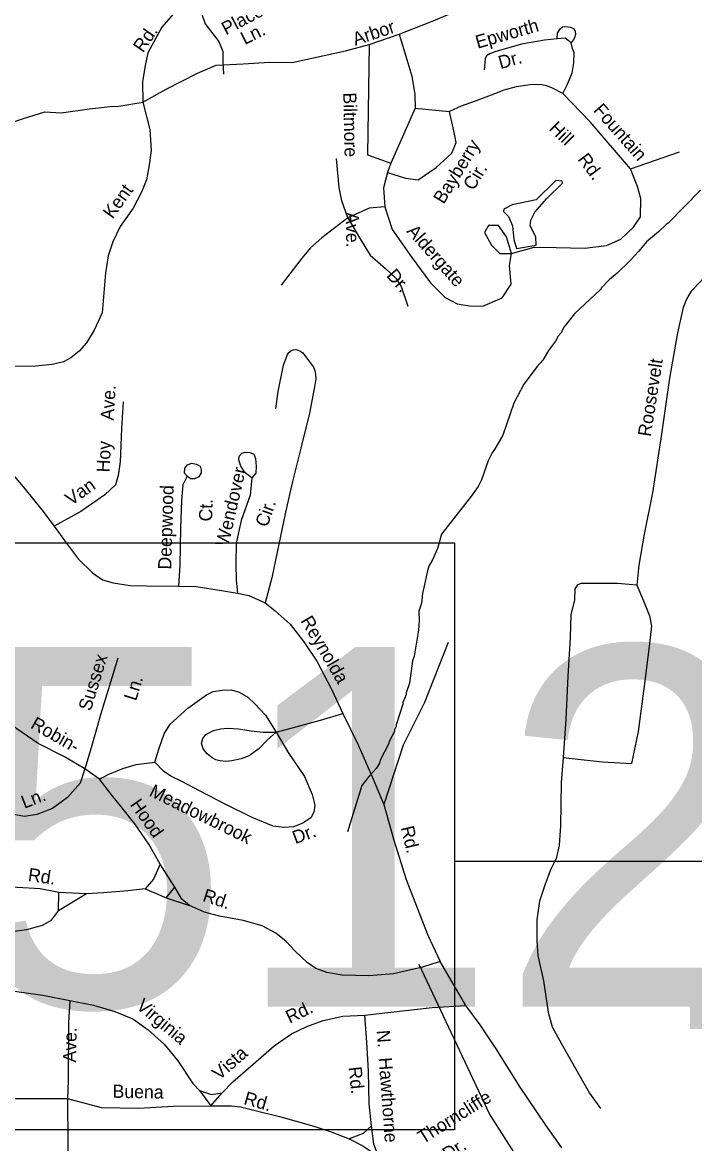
# Model space of a CAD drawing. Extents: x 1551653 to 1702041, y 811336 to 920032.
# Drawn here: x 1623759 to 1627102, y 859253 to 864827 of the extents above; entities that cross this region are included whole.
import ezdxf

# ---------------------------------------------------------------- set-up
doc = ezdxf.new("R2010")
doc.units = 0
for name, color, linetype in [('Old_Level_10', 7, 'Continuous'), ('Old_Level_3', 7, 'Continuous'), ('Old_Level_35', 7, 'Continuous'), ('Old_Level_4', 7, 'Continuous'), ('Old_Level_59', 7, 'Continuous'), ('Old_Level_62', 7, 'Continuous')]:
    doc.layers.add(name, color=color, linetype=linetype)

msp = doc.modelspace()

# ---------------------------------------------------------------- linework, layer by layer
at = {"layer": 'Old_Level_3'}
for points in [[(1625908.099, 859320.788), (1619071.581, 859320.788), (1619071.581, 862239.39), (1625908.099, 862239.39), (1625908.099, 860614.92), (1625908.099, 859320.788)], [(1625908.732, 860656.483), (1625995.984, 860656.483), (1627693.505, 860656.483), (1628512.004, 857639.692), (1629167.822, 855222.504), (1629168.24, 855220.962)]]:
    msp.add_lwpolyline(points, dxfattribs=at)
at = {"layer": 'Old_Level_35'}
for p, q in [((1624650.579, 864867.619), (1624668.219, 864820.546)), ((1624668.219, 864820.546), (1624706.439, 864770.531)), ((1624706.439, 864770.531), (1624735.838, 864732.284)), ((1624735.838, 864732.284), (1624756.418, 864682.269)), ((1625483.991, 864717.631), (1625632.244, 864768.709)), ((1624756.418, 864682.269), (1624756.418, 864635.196)), ((1624756.418, 864635.196), (1624759.553, 864569.308)), ((1625712.631, 864399.788), (1625591.112, 864127.374)), ((1625712.631, 864399.788), (1625882.254, 864384.056)), ((1626783.635, 864098.978), (1627026.652, 864183.424)), ((1625591.112, 864127.374), (1625574.099, 864081.161)), ((1624142.818, 861064.883), (1624069.617, 861115.995)), ((1624517.513, 860526.984), (1624443.405, 860642.151)), ((1623938.813, 860409.254), (1623940.28, 860501.275)), ((1624078.025, 860494.881), (1623938.813, 860409.254)), ((1624078.025, 860494.881), (1623940.28, 860501.275)), ((1624473.421, 860474.451), (1624517.513, 860526.984)), ((1624473.421, 860474.451), (1624589.901, 860435.865)), ((1625963.566, 859939.134), (1625835.732, 860157.847)), ((1624639.484, 859516.349), (1624696.193, 859441.356)), ((1624696.193, 859441.356), (1624753.103, 859504.436))]:
    msp.add_line(p, q, dxfattribs=at)
for points in [[(1625632.244, 864768.709), (1625792.648, 864831.948), (1625940.901, 864892.755), (1626123.179, 864965.722), (1626276.305, 865017.217), (1626435.713, 865087.084)], [(1624664.17, 865046.378), (1624566.956, 864934.494), (1624452.871, 864803.178), (1624382.413, 864674.808), (1624369.352, 864613.037), (1624355.656, 864530.765), (1624358.354, 864430.022)], [(1626417.66, 864745), (1626420.229, 864772.963), (1626432.476, 864794.724), (1626445.071, 864804.075), (1626462.345, 864807.126), (1626484.49, 864803.875), (1626498.946, 864796.378), (1626508.49, 864783.579), (1626509.159, 864767.155), (1626505.212, 864750.226), (1626497.384, 864739.18), (1626487.312, 864725.974)], [(1625632.244, 864768.709), (1625671.314, 864643.014), (1625695.618, 864560.317), (1625710.2, 864467.891), (1625712.631, 864399.788)], [(1626417.66, 864745), (1626355.685, 864738.051), (1626241.417, 864717.956), (1626155.072, 864693.294), (1626113.021, 864682.143), (1626082.772, 864670.548), (1626067.559, 864660.453), (1626060.439, 864644.987), (1626055.544, 864591.057)], [(1626487.312, 864725.974), (1626457.748, 864748.386), (1626417.66, 864745)], [(1626447.151, 864472.648), (1626469.933, 864520.414), (1626492.873, 864575.978), (1626501.688, 864625.827), (1626502.499, 864675.64), (1626494.743, 864697.809), (1626487.312, 864725.974)], [(1624358.354, 864430.022), (1624473.646, 864494.745), (1624630.288, 864574.546), (1624722.642, 864613.462), (1624856.312, 864620.759), (1624988.153, 864629.263), (1625099.974, 864627.396), (1625206.286, 864649.946), (1625366.048, 864686.084), (1625483.991, 864717.631)], [(1625483.991, 864717.631), (1625474.454, 864168.722), (1625591.112, 864127.374)], [(1626447.151, 864472.648), (1626395.668, 864499.508), (1626366.899, 864511.497), (1626334.025, 864518.57), (1626283.966, 864516.982), (1626213.917, 864506.598), (1626153.736, 864489.41), (1626089.396, 864464.499), (1626010.974, 864435.873), (1625940.633, 864411.087), (1625882.254, 864384.056)], [(1626783.635, 864098.978), (1626581.894, 864331.792), (1626447.151, 864472.648)], [(1623675.772, 864319.965), (1623764.2, 864348.59), (1623870.552, 864382.852), (1623952.484, 864377.386), (1624093.176, 864396.991), (1624195.252, 864409.152), (1624239.487, 864410.968), (1624358.354, 864430.022)], [(1624358.354, 864430.022), (1624392.112, 864294.835), (1624399.492, 864190.334), (1624390.23, 864118.484), (1624376.431, 864044.691), (1624351.369, 863983.166), (1624310.075, 863903.87), (1624244.797, 863812.945), (1624209.41, 863735.619), (1624186.385, 863666.049), (1624172.881, 863582.276), (1624163.048, 863462.608), (1624155.624, 863382.713), (1624116.273, 863297.464), (1624077.366, 863234.019), (1624040.709, 863192.739), (1624000.21, 863159.34), (1623963.797, 863139.869), (1623907.701, 863126.798), (1623823.685, 863118.297), (1623717.783, 863116.043)], [(1625574.099, 864081.161), (1625664.023, 864051.974), (1625727.212, 864044.677), (1625817.136, 864105.484), (1625894.908, 864176.02), (1625916.781, 864229.529), (1625904.63, 864287.904), (1625882.254, 864384.056)], [(1625377.221, 863855.284), (1625348.057, 863940.413), (1625333.475, 864006.085), (1625321.323, 864149.588)], [(1625574.099, 864081.161), (1625554.696, 864004.255), (1625561.986, 863909.396)], [(1626191.453, 863678.331), (1626303.25, 863709.951), (1626412.616, 863707.518), (1626556.008, 863705.087), (1626662.945, 863717.248), (1626735.028, 863748.732), (1626798.218, 863809.538), (1626832.243, 863860.616), (1626834.673, 863950.61), (1626817.661, 864011.416), (1626783.635, 864098.978)], [(1625561.986, 863909.396), (1625484.158, 863903.93), (1625377.221, 863855.284)], [(1625561.986, 863909.396), (1625598.442, 863797.513), (1625695.657, 863658.874), (1625788.011, 863532.396), (1625860.922, 863459.428), (1625921.681, 863427.809), (1625982.441, 863418.079), (1626048.061, 863415.647), (1626145.276, 863456.996), (1626189.023, 863525.099), (1626181.731, 863617.525), (1626191.453, 863678.331)], [(1625377.221, 863855.284), (1625248.349, 863756.614), (1625192.451, 863705.536), (1625148.705, 863654.458), (1625046.629, 863520.684)], [(1625377.221, 863855.284), (1625430.628, 863763.91), (1625488.957, 863669.052), (1625564.298, 863603.381), (1625615.336, 863554.736), (1625642.07, 863513.387), (1625676.095, 863416.097)], [(1626191.453, 863678.331), (1626167.149, 863761.029), (1626125.833, 863816.97), (1626077.225, 863816.97), (1626057.782, 863782.919), (1626091.807, 863719.68), (1626133.124, 863678.331), (1626181.731, 863678.331), (1626191.453, 863678.331)], [(1627372.638, 863643.618), (1627304.456, 863626.593), (1627208.029, 863588.326), (1627135.276, 863543.378), (1627084.378, 863490.38), (1627061.756, 863450.616), (1627045.103, 863408.93), (1627017.147, 863283.628), (1626977.357, 863058.31), (1626936.875, 862779.174), (1626892.147, 862487.921), (1626850.766, 862282.846), (1626824.237, 862129.297), (1626814.608, 862029.438)], [(1625018.798, 862904.941), (1625030.182, 862992.559), (1625058.223, 863122.064), (1625077.121, 863175.712), (1625083.519, 863185.387), (1625093.492, 863193.589), (1625105.405, 863198.95), (1625119.457, 863201.066), (1625139.342, 863194.859), (1625153.341, 863184.57), (1625182.577, 863146.155), (1625205.93, 863113.665), (1625213.39, 863096.703), (1625217.367, 863075.61), (1625217.747, 863054.99), (1625212.347, 863015.679), (1625186.268, 862884.134), (1625143.332, 862710.91), (1625102.718, 862543.64), (1625068.23, 862392.255), (1624998.768, 862065.681), (1624966.222, 861940.872)], [(1624260.325, 862941.145), (1624252.011, 862807.438), (1624245.246, 862641.684), (1624236.066, 862573.833), (1624221.329, 862528.105), (1624168.704, 862478.945), (1624049.338, 862394.919), (1623916.316, 862322.251)], [(1623611.862, 862694.237), (1623772.968, 862506.435), (1623855.117, 862403.112), (1623916.316, 862322.251)], [(1624899.201, 862562.977), (1624867.679, 862587.432), (1624846.147, 862620.887), (1624834.769, 862651.933), (1624837.151, 862670.696), (1624850.442, 862684.633), (1624867.348, 862689.496), (1624891.35, 862689.007), (1624909.195, 862680.841), (1624918.752, 862658.636), (1624922.138, 862618.544), (1624919.49, 862586.579), (1624899.201, 862562.977)], [(1624577.778, 862570.3), (1624565.895, 862586.349), (1624566.404, 862611.353), (1624580.951, 862628.069), (1624600.718, 862635.87), (1624624.642, 862631.382), (1624642.443, 862621.218), (1624648.037, 862601.094), (1624647.955, 862587.088), (1624636.551, 862567.508), (1624615.14, 862557.734), (1624595.741, 862558.128), (1624577.778, 862570.3)], [(1624577.778, 862570.3), (1624557.119, 862528.495), (1624549.737, 862450.802), (1624545.537, 862312.81), (1624542.408, 862128.972), (1624536.072, 862023.841)], [(1624899.201, 862562.977), (1624891.856, 862477.078), (1624847.653, 862349.903), (1624821.977, 862238.365), (1624820.271, 862134.539), (1624822.847, 862054.444), (1624829.126, 861989.08)], [(1623916.316, 862322.251), (1623976.087, 862240.004), (1624036.506, 862160.536), (1624108.221, 862090.669), (1624156.785, 862055.152), (1624210.952, 862040.198), (1624295.003, 862027.113), (1624376.24, 862026.485), (1624536.072, 862023.841)], [(1624536.072, 862023.841), (1624623.894, 862022.46), (1624739.589, 862004.504), (1624829.126, 861989.08)], [(1626814.608, 862029.438), (1626718.909, 862036.984), (1626565.038, 862037.502), (1626537.033, 862038.073), (1626518.87, 862030.435), (1626506.659, 862010.471), (1626503.726, 861954.7), (1626486.462, 861883.011), (1626482.748, 861769.022), (1626471.456, 861577.346), (1626461.918, 861363.619), (1626448.824, 861171.979)], [(1626814.608, 862029.438), (1626847.236, 861951.134), (1626877.944, 861876.669), (1626887.088, 861824.455), (1626875.461, 861724.635), (1626850.244, 861527.237), (1626820.658, 861301.91), (1626788.007, 861142.484)], [(1624829.126, 861989.08), (1624884.933, 861978.142), (1624966.222, 861940.872)], [(1624966.222, 861940.872), (1625015.461, 861902.053), (1625090.34, 861834.898), (1625158.811, 861747.86), (1625223.079, 861650.902), (1625296.697, 861511.732), (1625352.678, 861390.929)], [(1625875.801, 861744.246), (1625757.927, 861445.989), (1625653.026, 861233.885), (1625557.002, 860937.934)], [(1624233.858, 861666.171), (1624204.268, 861568.717), (1624147.287, 861383.77), (1624100.752, 861220.624), (1624069.617, 861115.995)], [(1624069.617, 861115.995), (1623968.77, 861175.673), (1623838.042, 861241.762), (1623731.277, 861315.368), (1623587.639, 861445.555), (1623444.282, 861614.654)], [(1624417.083, 861149.568), (1624438.182, 861213.176), (1624463.369, 861290.709), (1624494.147, 861338.11), (1624581.387, 861416.785), (1624674.382, 861483.136), (1624708.556, 861500.653), (1624752.725, 861507.759), (1624796.574, 861509.071), (1624836.341, 861496.46), (1624880.064, 861471.759), (1624915.422, 861439.222), (1624968.496, 861382.316), (1625021.006, 861297.602)], [(1625021.006, 861297.602), (1625107.354, 861322.267), (1625241.75, 861357.96), (1625352.678, 861390.929)], [(1625352.678, 861390.929), (1625427.97, 861235.716), (1625503.144, 861064.696), (1625557.002, 860937.934)], [(1624069.617, 861115.995), (1624047.169, 861045.211), (1623984.095, 860974.25), (1623909.345, 860919.535), (1623830.877, 860888.712), (1623768.863, 860879.762), (1623699.096, 860892.983), (1623626.185, 860935.445), (1623546.897, 860972.672), (1623488.655, 861028.998), (1623414.69, 861097.468), (1623363.693, 861158.134), (1623312.492, 861198.997), (1623249.09, 861230.099), (1623197.404, 861246.956), (1623123.706, 861254.056), (1623053.979, 861269.275)], [(1625021.006, 861297.602), (1625081.193, 861196.726), (1625161.219, 861077.438), (1625199.641, 860988.81), (1625212.751, 860934.712), (1625208.259, 860900.785), (1625193.692, 860873.065), (1625153.315, 860845.667), (1625107.137, 860828.397), (1625059.021, 860823.768), (1625005.33, 860830.661), (1624902.148, 860873.777), (1624767.42, 860939.945), (1624640.488, 861005.959), (1624551.404, 861053.39), (1624497.919, 861080.289), (1624460.4, 861104.863), (1624417.083, 861149.568)], [(1625021.006, 861297.602), (1624978.224, 861260.05), (1624935.914, 861216.283), (1624887.148, 861179.853), (1624846.423, 861164.869), (1624800.803, 861155.191), (1624770.74, 861152.999), (1624741.971, 861155.181), (1624721.075, 861161.011), (1624703.264, 861170.775), (1624677.666, 861191.306), (1624657.949, 861215.519), (1624650.514, 861243.685), (1624655.793, 861267.192), (1624671.21, 861287.29), (1624709.425, 861306.726), (1624743.405, 861314.643), (1624781.482, 861317.471), (1624833.45, 861314.616), (1624897.302, 861305.515), (1624956.993, 861298.701), (1625021.006, 861297.602)], [(1626448.824, 861171.979), (1626438.906, 861048.111), (1626435.327, 860832.262), (1626427.784, 860736.563), (1626412.643, 860670.835), (1626385.662, 860613.348), (1626356.518, 860537.899), (1626331.285, 860458.165), (1626317.581, 860364.592), (1626317.873, 860260.527), (1626322.817, 860188.585), (1626350.668, 860062.152), (1626374.11, 859905.791), (1626392.853, 859833.57), (1626439.366, 859748.98), (1626503.545, 859637.815), (1626579.247, 859502.806), (1626633.955, 859427.855)], [(1626448.824, 861171.979), (1626522.715, 861164.676), (1626644.3, 861150.801), (1626788.007, 861142.484)], [(1624142.818, 861064.883), (1624186.293, 861087.212), (1624258.76, 861118.16), (1624324.977, 861137.028), (1624417.083, 861149.568)], [(1624443.405, 860642.151), (1624387.182, 860740.946), (1624318.796, 860842.19), (1624246.365, 860931.307), (1624203.448, 860985.808), (1624142.818, 861064.883)], [(1625557.002, 860937.934), (1625606.044, 860761.242), (1625666.723, 860566.301), (1625722.297, 860425.497), (1625775.955, 860288.733), (1625835.732, 860157.847)], [(1623940.28, 860501.275), (1623846.786, 860518.781), (1623733.082, 860526.491), (1623649.148, 860531.997), (1623579.86, 860569.024), (1623504.782, 860626.176), (1623472.341, 860644.844), (1623427.452, 860661.363), (1623333.877, 860674.87)], [(1624443.405, 860642.151), (1624411.076, 860567.564), (1624370.295, 860520.166)], [(1624370.295, 860520.166), (1624284.232, 860509.507), (1624162.166, 860499.575), (1624078.025, 860494.881)], [(1624370.295, 860520.166), (1624421.67, 860497.912), (1624473.421, 860474.451)], [(1624589.901, 860435.865), (1624552.342, 860468.447), (1624517.513, 860526.984)], [(1625835.732, 860157.847), (1625749.505, 860129.179), (1625604.984, 860097.493), (1625481.31, 860087.194), (1625349.289, 860089.675), (1625273.518, 860103.018), (1625217.915, 860123.956), (1625174.473, 860152.654), (1625115.392, 860209.484), (1625070.356, 860258.224), (1625019.159, 860299.084), (1624951.672, 860336.075), (1624856.341, 860361.623), (1624738.723, 860383.618), (1624665.272, 860402.719), (1624589.901, 860435.865)], [(1623509.618, 860312.305), (1623595.556, 860306.958), (1623693.377, 860305.373), (1623781.474, 860317.794), (1623859.738, 860338.618), (1623904.076, 860363.933), (1623938.813, 860409.254)], [(1623508.942, 860022.555), (1623646.766, 860020.16), (1623860.086, 859990.817), (1623995.43, 859964.659)], [(1623995.43, 859964.659), (1623987.556, 859852.756), (1623986.962, 859567.008), (1623983.908, 859476.869)], [(1623995.43, 859964.659), (1624113.006, 859940.663), (1624218.219, 859908.911), (1624307.546, 859873.478), (1624384.668, 859818.284), (1624463.467, 859747.047), (1624532.02, 859664.01), (1624605.964, 859550.847), (1624639.484, 859516.349)], [(1625462.714, 859890.663), (1625576.864, 859904.957), (1625797.077, 859929.304), (1625963.566, 859939.134)], [(1626441.475, 859231.648), (1626361.328, 859344.935), (1626230.793, 859538.892), (1626117.778, 859718.685), (1626035.876, 859844.012), (1625963.566, 859939.134)], [(1624753.103, 859504.436), (1624806.049, 859559.594), (1624907.295, 859647.992), (1625010.779, 859738.143), (1625097.656, 859798.816), (1625174.04, 859835.486), (1625254.463, 859864.071), (1625352.77, 859886.489), (1625462.714, 859890.663)], [(1625495.575, 859340.49), (1625483.403, 859450.598), (1625480.083, 859612.556), (1625472.599, 859756.588), (1625462.714, 859890.663)], [(1624639.484, 859516.349), (1624699.126, 859497.13), (1624753.103, 859504.436)], [(1623493.649, 859475.217), (1623656.275, 859476.42), (1623840.192, 859477.29), (1623983.908, 859476.869)], [(1623983.908, 859476.869), (1623985.755, 859251.058), (1623983.57, 859005.366), (1623978.029, 858781.554), (1623983.265, 858615.554)], [(1623983.908, 859476.869), (1624150.519, 859432.419), (1624338.356, 859429.207), (1624508.234, 859438.567), (1624696.193, 859441.356)], [(1624696.193, 859441.356), (1624798.641, 859441.08), (1624843.345, 859435.168), (1624897.515, 859422.265), (1625044.854, 859385.857), (1625207.994, 859339.122), (1625295.287, 859311.737), (1625384.614, 859276.304)], [(1625495.575, 859340.49), (1625452.996, 859303.134), (1625384.614, 859276.304)], [(1625529.105, 859188.125), (1625506.156, 859250.424), (1625495.575, 859340.49)], [(1625384.614, 859276.304), (1625452.14, 859241.317), (1625529.105, 859188.125)]]:
    msp.add_lwpolyline(points, dxfattribs=at)
at = {"layer": 'Old_Level_59'}
msp.add_lwpolyline([(1627327.507, 858118.578), (1626992.913, 858301.575), (1626794.852, 858440.654), (1626787.778, 858499.914), (1626689.763, 858675.849), (1626253.822, 859131.167), (1626081.784, 859400.554), (1625731.744, 860143.683)], dxfattribs=at)
at = {"layer": 'Old_Level_62'}
for points in [[(1626203.482, 863746.838), (1626215.99, 863703.059), (1626314.005, 863719.566), (1626312.16, 863758.628), (1626284.478, 863817.068), (1626287.041, 863843.11), (1626307.443, 863884.12), (1626366.191, 863950.762), (1626444.316, 864027.964), (1626443.598, 864037.909), (1626411.61, 864040.575), (1626314.21, 863944.508), (1626195.382, 863919.081), (1626152.322, 863898.166), (1626152.219, 863887.401), (1626175.595, 863861.154), (1626196.51, 863815.735), (1626203.482, 863746.838)], [(1627130.522, 863992.49), (1626970.377, 863828.756), (1626960.329, 863822.912), (1626921.779, 863785.387), (1626863.135, 863736.277), (1626824.585, 863688.808), (1626779.883, 863641.441), (1626717.137, 863580.335), (1626676.64, 863546.912), (1626638.192, 863507.439), (1626634.091, 863499.545), (1626504.498, 863377.334), (1626453.646, 863314.075), (1626437.241, 863282.292), (1626422.99, 863266.503), (1626410.687, 863242.717), (1626376.033, 863195.145), (1626347.429, 863147.573), (1626319.029, 863115.995), (1626251.874, 863028.95), (1626202.559, 862933.704), (1626148.426, 862774.481), (1626107.518, 862703.02), (1626095.215, 862687.231), (1626074.709, 862647.553), (1626041.491, 862551.999), (1626024.984, 862520.216), (1625992.381, 862472.747), (1625843.923, 862282.868), (1625822.905, 862211.1), (1625798.197, 862155.531), (1625779.742, 862123.748), (1625773.385, 862099.859), (1625747.856, 861988.208), (1625743.243, 861940.329), (1625730.734, 861900.446), (1625732.067, 861852.464), (1625729.402, 861804.584), (1625707.666, 861676.837), (1625699.361, 861652.948), (1625683.778, 861541.195), (1625667.168, 861493.52), (1625667.066, 861485.523), (1625650.559, 861445.743), (1625650.457, 861437.746), (1625617.033, 861334.195), (1625616.931, 861326.198), (1625608.728, 861310.306), (1625608.626, 861302.309), (1625583.917, 861254.737), (1625579.714, 861238.743), (1625538.703, 861159.388), (1625534.5, 861143.394), (1625520.146, 861119.608), (1625483.647, 861080.135), (1625447.045, 861032.666), (1625375.789, 860803.52)]]:
    msp.add_lwpolyline(points, dxfattribs=at)

# ---------------------------------------------------------------- texts
at = {"layer": 'Old_Level_10'}
for s, height, rotation, p in [('Place', 65.6167, 28.014825, (1624771.535, 864761.791)), ('Epworth', 65.6167, 15.940508, (1626022.692, 864695.767)), ('Rd.', 65.6167, 55.173367, (1624358.406, 864672.422)), ('Ln.', 65.6166, 26.720517, (1624865.359, 864713.925)), ('Arbor', 65.6167, 18.598006, (1625414.449, 864710.255)), ('Dr.', 65.6167, 15.940508, (1626136.602, 864594.059)), ('Biltmore', 65.6167, 271.263175, (1625354.394, 864477.95)), ('Fountain', 65.6167, 311.453981, (1626595.082, 864388.365)), ('Hill', 65.6167, 315.407489, (1626373.582, 864295.115)), ('Bayberry', 65.6167, 58.39965, (1625853.81, 863919.736)), ('Rd.', 65.6167, 306.889269, (1626517.395, 864145.697)), ('Cir.', 65.6167, 58.39965, (1626002.139, 863986.904)), ('Kent', 65.6167, 54.323906, (1624207.698, 863846.283)), ('Ave.', 65.6167, 270.550786, (1625367.589, 863882.411)), ('Aldergate', 65.6167, 311.542011, (1625666.494, 863786.633)), ('Dr.', 65.6167, 311.542011, (1625566.09, 863565.934)), ('Roosevelt', 65.6167, 81.098356, (1626883.716, 862764.522)), ('Ave.', 65.6167, 86.442047, (1624212.597, 862846.728)), ('Hoy', 65.6167, 87.662833, (1624193.237, 862588.815)), ('Wendover', 65.6167, 77.036528, (1624782.347, 862218.019)), ('Van', 65.6167, 35.142775, (1624001.315, 862422.211)), ('Deepwood', 65.6167, 88.256872, (1624498.852, 862105.986)), ('Ct.', 65.6167, 88.256872, (1624702.231, 862344.981)), ('Cir.', 65.6167, 70.833892, (1624976.801, 862313.239)), ('Reynolda', 65.6167, 300.529583, (1625140.604, 861852.644)), ('Sussex', 65.6167, 72.876133, (1624098.602, 861399.227)), ('Ln.', 65.6167, 72.876133, (1624324.274, 861450.449)), ('Robin-', 65.6167, 330.223506, (1623794.837, 861321.471)), ('Ln.', 65.6167, 21.445736, (1623768.698, 860916.833)), ('Meadowbrook', 65.61666, 333.843244, (1624384.648, 860983.477)), ('Hood', 65.6167, 305.336147, (1624291.624, 860937.758)), ('Rd.', 65.6167, 283.410875, (1625640.359, 860824.052)), ('Dr.', 65.6167, 20.505619, (1625116.479, 860741.036)), ('Rd.', 65.6167, 351.783758, (1623784.08, 860558.984)), ('Rd.', 65.6167, 341.916008, (1624651.143, 860459.536)), ('Virginia', 65.6167, 320.019625, (1624320.953, 859928.875)), ('Rd.', 65.6167, 25.644286, (1625087.958, 859848.417)), ('Ave.', 65.6167, 88.759014, (1624025.954, 859655.473)), ('N.  Hawthorne', 65.61666, 274.216717, (1625520.727, 859815.184)), ('Vista', 65.6167, 41.124353, (1624737.884, 859565.204)), ('Rd.', 65.6167, 276.308147, (1625380.212, 859632.419)), ('Buena', 65.6167, 359.020364, (1624207.073, 859480.686)), ('Rd.', 65.6167, 344.014283, (1624855.982, 859450.304)), ('Thorncliffe', 65.61666, 32.024767, (1625750.885, 859249.489)), ('Dr.', 65.6167, 32.024767, (1625874.154, 859166.351))]:
    msp.add_text(s, height=height, rotation=rotation, dxfattribs=at).set_placement(p)
at = {"layer": 'Old_Level_3'}
msp.add_text('B-4512', height=1788.0542, dxfattribs=at).set_placement((1619746.3, 859933.988))
at = {"layer": 'Old_Level_4'}
msp.add_text('J172', height=1049.8646, dxfattribs=at).set_placement((1626796.39, 858888.334))

doc.saveas('drawing.dxf')
